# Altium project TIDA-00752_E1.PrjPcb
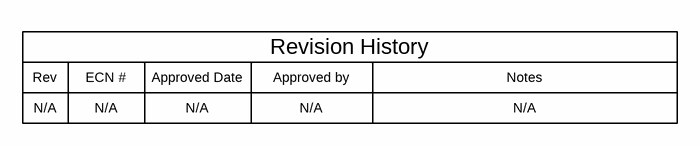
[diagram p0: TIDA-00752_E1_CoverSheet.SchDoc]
CopyrightYear: 2015; EVM_Orderable: N/A; PCB_Layout: SY; PCB_Rev: E1; PRJ_Customer: Public Release; PRJ_Engineer: SY; PRJ_Number: TIDA-00752; PRJ_Title: 2-Wire Galvanically Isolated IC Temperature Sensor with Pulse Count Interface; SCH_Rev: E1; TechSupport: http://www.ti.com/support; TID: TIDA-00752
3 sheets, 89 parts. Net scope: global (net labels, ports and power ports of the same name join across sheets).
Board file: TIDA-00752_E1_TID.PcbDoc
Sheets:
  TIDA-00752_E1_CoverSheet.SchDoc
  TIDA-00752_E1_MSP430_LMT01.SchDoc
  TIDA-00752_E1_TID_Hardware.SchDoc

## Sheet TIDA-00752_E1_CoverSheet.SchDoc: System Block Diagram
size 431 x 279 mm; Date: Not shown in title block; ApprovedBy: Not shown in title block; CheckedBy: Not shown in title block; Author: Not shown in title block; CompanyName: Not shown in title block; DrawnBy: SY; Engineer: Not shown in title block; Organization: Not shown in title block; Address1: Not shown in title block; Address2: Not shown in title block; Address3: Not shown in title block; Address4: Not shown in title block; DocumentNumber: 1; Revision: Use project parameter SCH_Rev; SheetNumber: 1; SheetTotal: 3; PageSetup: Record=PageOptions¦CenterHorizontal=True¦CenterVertical=True¦PrintScale=1.00¦XCorrection=1.00¦YCorrection=1.00¦PrintKind=0¦BorderSize=5000000¦LeftOffset=0¦BottomOffset=0¦Orientation=2¦PaperLength=1000¦PaperWidth=1000¦Scale=100¦PaperSource=15¦PrintQuality=600¦MediaType=1¦DitherType=10¦PaperKind=Letter¦PrintScaleMode=1

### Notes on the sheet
- Rev
- N/A
- ECN #
- Approved Date
- Approved by
- Revision History
- Notes

## Sheet TIDA-00752_E1_MSP430_LMT01.SchDoc: MSP430 MCU & LMT01 Interface Circuitry
size 431 x 279 mm; Date: Not shown in title block; ApprovedBy: Not shown in title block; CheckedBy: Not shown in title block; Author: Not shown in title block; CompanyName: Not shown in title block; DrawnBy: SY; Engineer: Not shown in title block; Organization: Not shown in title block; Address1: Not shown in title block; Address2: Not shown in title block; Address3: Not shown in title block; Address4: Not shown in title block; DocumentNumber: 1; Revision: Use project parameter SCH_Rev; SheetNumber: 2; SheetTotal: 3; PageSetup: Record=PageOptions¦CenterHorizontal=True¦CenterVertical=True¦PrintScale=1.00¦XCorrection=1.00¦YCorrection=1.00¦PrintKind=0¦BorderSize=5000000¦LeftOffset=0¦BottomOffset=0¦Orientation=2¦PaperLength=1000¦PaperWidth=1000¦Scale=100¦PaperSource=15¦PrintQuality=600¦MediaType=1¦DitherType=10¦PaperKind=Letter¦PrintScaleMode=1
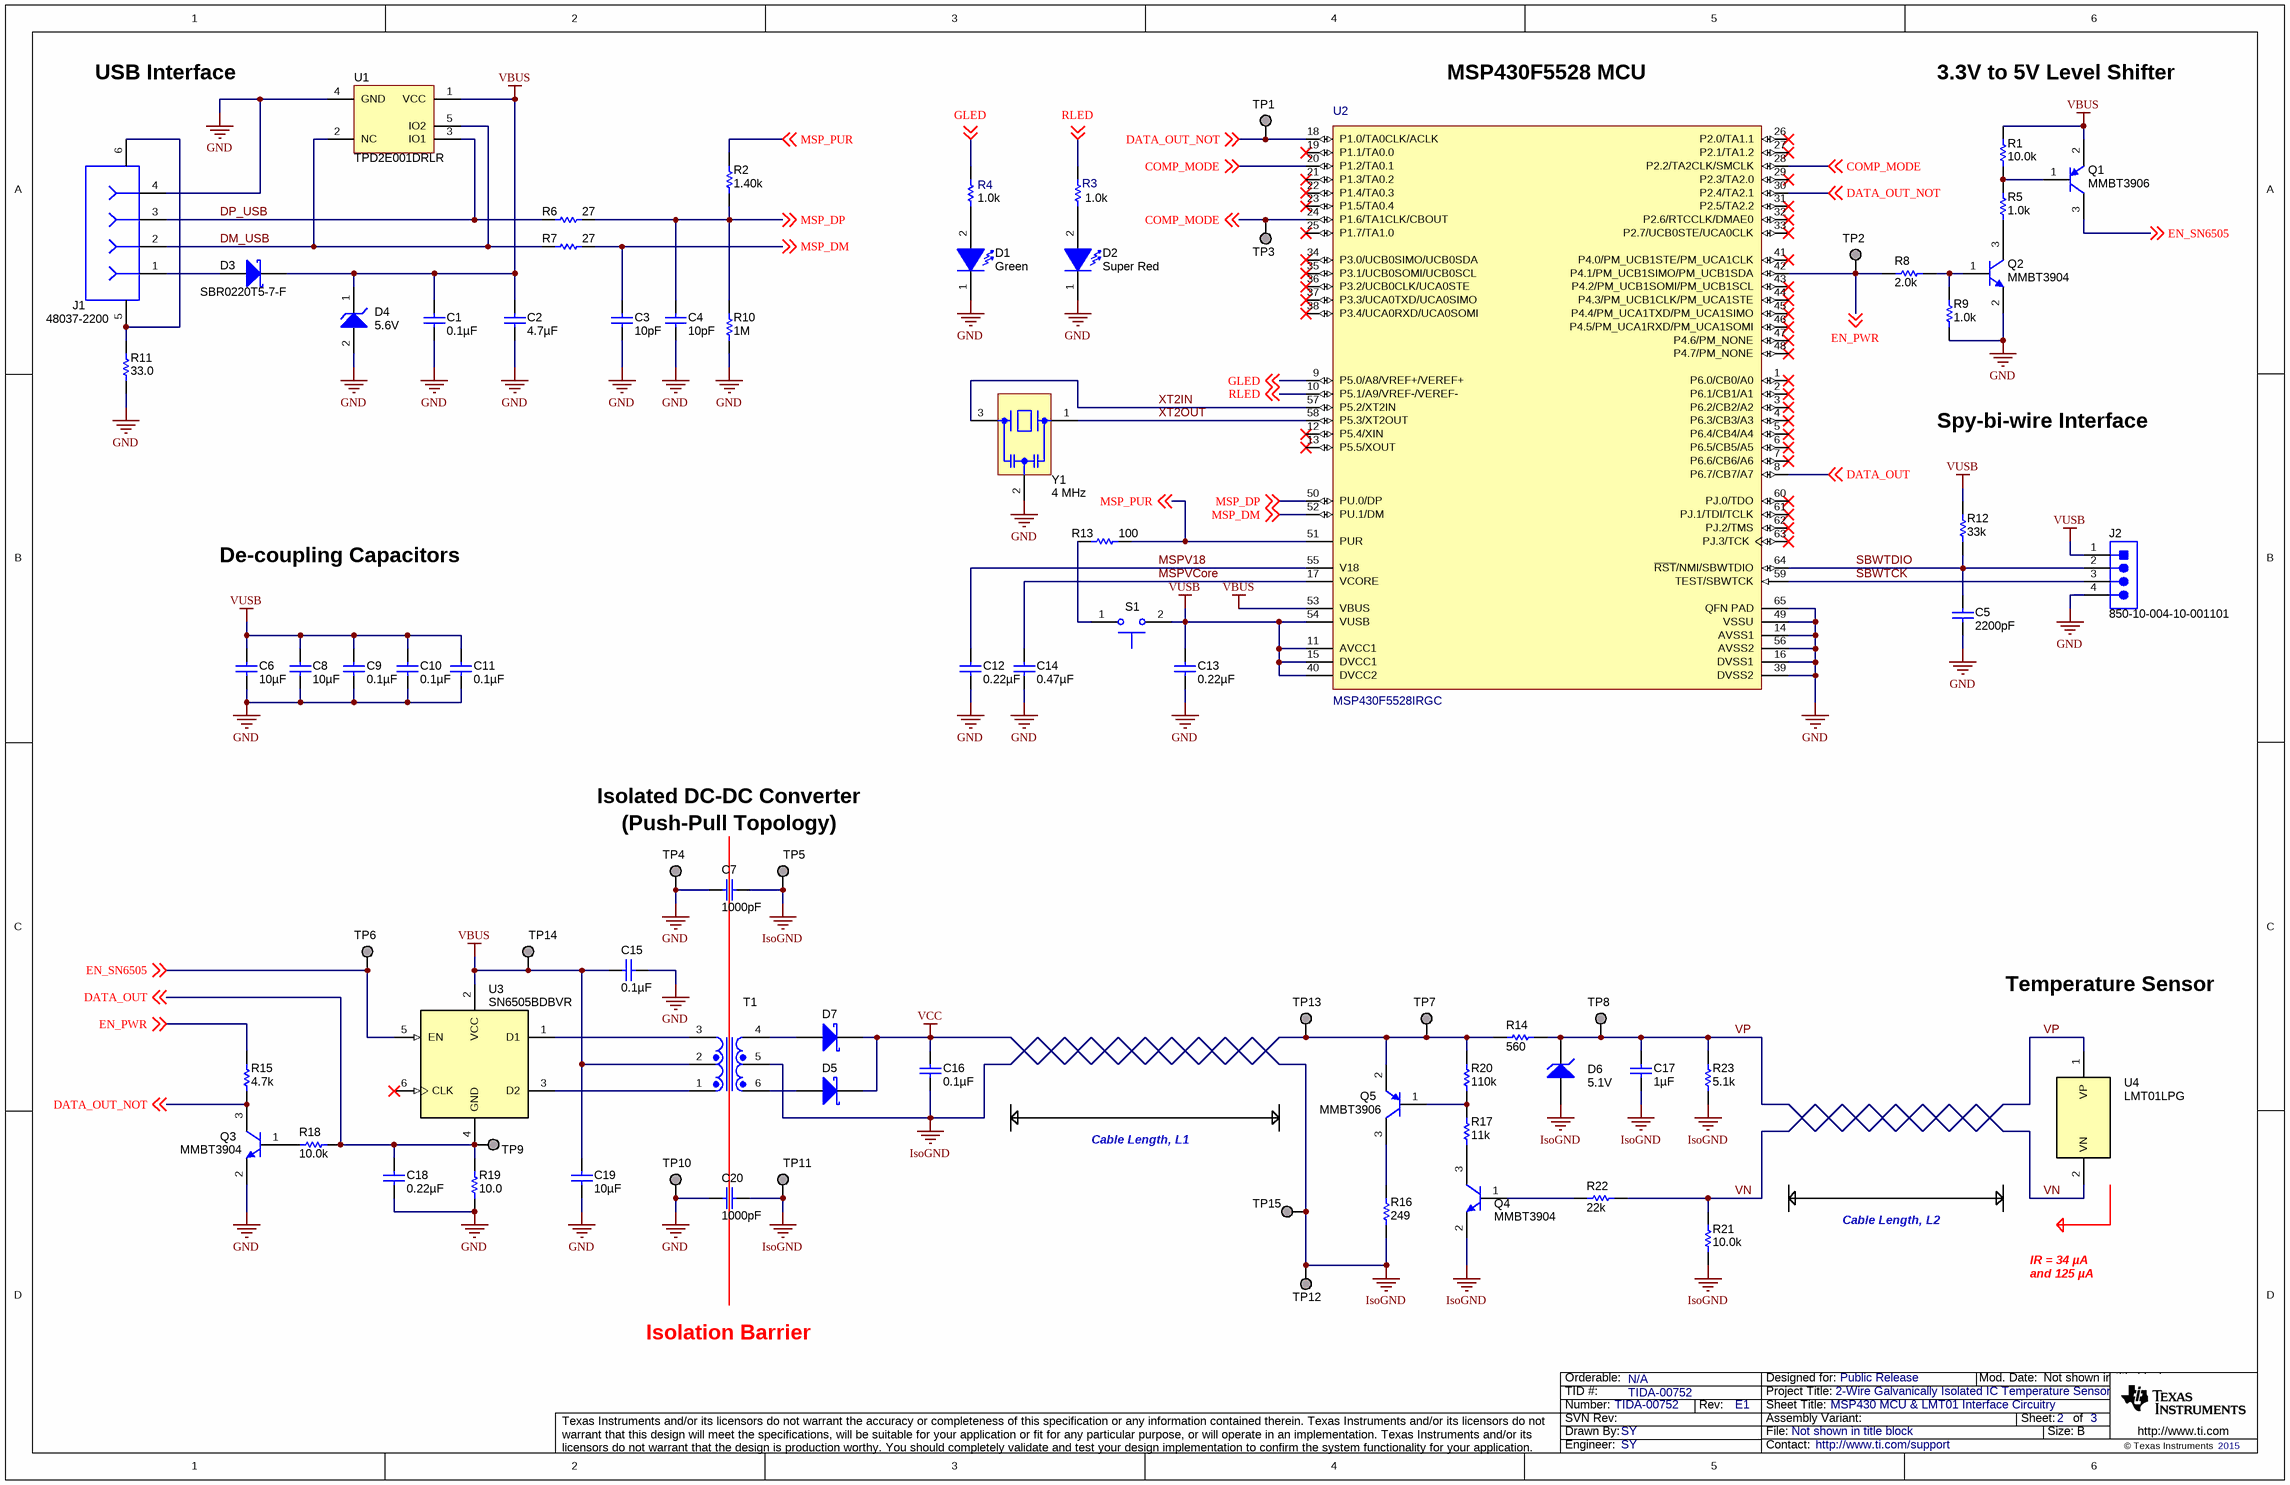
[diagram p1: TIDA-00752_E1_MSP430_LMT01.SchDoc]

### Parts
C1  ValueDisplayed: 0.1µF  [0402]  (hidden comment: C1005X7R1H104K050BB)
C2  ValueDisplayed: 4.7µF  [0603]  (hidden comment: 0603ZD475KAT2A)
C3  ValueDisplayed: 10pF  [0402]  (hidden comment: 500R07S100JV4T)
C4  ValueDisplayed: 10pF  [0402]  (hidden comment: 500R07S100JV4T)
C5  ValueDisplayed: 2200pF  [0402]  (hidden comment: GRM155R70J222KA01D)
C6  ValueDisplayed: 10µF  [0805_145]  (hidden comment: C2012X7R1A106K125AC)
C7  ValueDisplayed: 1000pF  [1206_190]  (hidden comment: 202R18W102KV4E)
C8  ValueDisplayed: 10µF  [0805_145]  (hidden comment: C2012X7R1A106K125AC)
C9  ValueDisplayed: 0.1µF  [0402]  (hidden comment: C1005X7R1H104K050BB)
C10  ValueDisplayed: 0.1µF  [0402]  (hidden comment: C1005X7R1H104K050BB)
C11  ValueDisplayed: 0.1µF  [0402]  (hidden comment: C1005X7R1H104K050BB)
C12  ValueDisplayed: 0.22µF  [0402]  (hidden comment: GRM155R61A224KE19D)
C13  ValueDisplayed: 0.22µF  [0402]  (hidden comment: GRM155R61A224KE19D)
C14  ValueDisplayed: 0.47µF  [0402]  (hidden comment: C1005X5R1A474K050BB)
C15  ValueDisplayed: 0.1µF  [0402]  (hidden comment: C1005X7R1H104K050BB)
C16  ValueDisplayed: 0.1µF  [0603]  (hidden comment: 06033C104JAT2A)
C17  ValueDisplayed: 1µF  [0603]  (hidden comment: GRM188R71A105KA61D)
C18  ValueDisplayed: 0.22µF  [0402]  (hidden comment: GRM155R71C224KA12D)
C19  ValueDisplayed: 10µF  [0805_145]  (hidden comment: EMK212BB7106MG-T)
C20  ValueDisplayed: 1000pF  [1206_190]  (hidden comment: 202R18W102KV4E)
D1  value Green  [WL-SMCW_GREEN]  (hidden comment: 150060VS75000)
D2  value Super Red  [WL-SMCW_RED]  (hidden comment: 150060SS75000)
D3  SBR0220T5-7-F  [SOD-523]
D4  value 5.6V  [SOD-123]  (hidden comment: MMSZ5232B-7-F)
D5  MBR0540T1G  [SOD-123]  (value not drawn)
D6  value 5.1V  [SOD-323F]  (hidden comment: D3Z5V1BF-7)
D7  MBR0540T1G  [SOD-123]  (value not drawn)
J1  48037-2200  [CONN_USB_0480372200]
J2  850-10-004-10-001101  [Preci-dip_850-xx-004-10-001101]
Q1  MMBT3906  [SOT-23]
Q2  MMBT3904  [SOT-23]
Q3  MMBT3904  [SOT-23]
Q4  MMBT3904  [SOT-23]
Q5  MMBT3906  [SOT-23]
R1  ValueDisplayed: 10.0k  [0402]  (hidden comment: CRCW040210K0FKED)
R2  ValueDisplayed: 1.40k  [0402]  (hidden comment: ERJ-2RKF1401X)
R3  value 1.0k  [0402]  (hidden comment: CRCW04021K00JNED)
R4  value 1.0k  [0402]  (hidden comment: CRCW04021K00JNED)
R5  ValueDisplayed: 1.0k  [0402]  (hidden comment: CRCW04021K00JNED)
R6  ValueDisplayed: 27  [0402]  (hidden comment: CRCW040227R0JNED)
R7  ValueDisplayed: 27  [0402]  (hidden comment: CRCW040227R0JNED)
R8  ValueDisplayed: 2.0k  [0402]  (hidden comment: CRCW04022K00JNED)
R9  ValueDisplayed: 1.0k  [0402]  (hidden comment: CRCW04021K00JNED)
R10  value 1M  [0402]  (hidden comment: CRCW04021M00JNED)
R11  ValueDisplayed: 33.0  [0603]  (hidden comment: CRCW060333R0FKEA)
R12  value 33k  [0402]  (hidden comment: CRCW040233K0JNED)
R13  ValueDisplayed: 100  [0402]  (hidden comment: ERJ-2RKF1000X)
R14  ValueDisplayed: 560  [0603]  (hidden comment: RC0603JR-07560RL)
R15  ValueDisplayed: 4.7k  [0402]  (hidden comment: CRCW04024K70JNED)
R16  ValueDisplayed: 249  [2512]  (hidden comment: CRCW2512249RFKEG)
R17  ValueDisplayed: 11k  [0402]  (hidden comment: CRCW040211K0JNED)
R18  ValueDisplayed: 10.0k  [0402]  (hidden comment: CRCW040210K0FKED)
R19  ValueDisplayed: 10.0  [0805_HV]  (hidden comment: RC0805FR-0710RL)
R20  ValueDisplayed: 110k  [0402]  (hidden comment: CRCW0402110KJNED)
R21  ValueDisplayed: 10.0k  [0402]  (hidden comment: CRCW040210K0FKED)
R22  ValueDisplayed: 22k  [0402]  (hidden comment: CRCW040222K0JNED)
R23  ValueDisplayed: 5.1k  [0402]  (hidden comment: CRCW04025K10JNED)
S1  SKRKAEE010  [SW_SKRKAEE010]  (value not drawn)
T1  760390014  [Wurth_760390013]  (value not drawn)
TP1  TESTPOINT  [TP_H045P075]  (value not drawn)  (no BOM)
TP2  TESTPOINT  [TP_H045P075]  (value not drawn)  (no BOM)
TP3  TESTPOINT  [TP_H045P075]  (value not drawn)  (no BOM)
TP4  TESTPOINT  [TP_H045P075]  (value not drawn)  (no BOM)
TP5  TESTPOINT  [TP_H045P075]  (value not drawn)  (no BOM)
TP6  TESTPOINT  [TP_H045P075]  (value not drawn)  (no BOM)
TP7  TESTPOINT  [TP_H045P075]  (value not drawn)  (no BOM)
TP8  TESTPOINT  [TP_H045P075]  (value not drawn)  (no BOM)
TP9  TESTPOINT  [TP_H045P075]  (value not drawn)  (no BOM)
TP10  TESTPOINT  [TP_H045P075]  (value not drawn)  (no BOM)
TP11  TESTPOINT  [TP_H045P075]  (value not drawn)  (no BOM)
TP12  TESTPOINT  [TP_H045P075]  (value not drawn)  (no BOM)
TP13  TESTPOINT  [TP_H045P075]  (value not drawn)  (no BOM)
TP14  TESTPOINT  [TP_H045P075]  (value not drawn)  (no BOM)
TP15  TESTPOINT  [TP_H045P075]  (value not drawn)  (no BOM)
U1  TPD2E001DRLR  [DRL0005A]
U2  MSP430F5528IRGC  [RGC0064B]
U3  SN6505BDBVR  [DBV0006A_N]
U4  LMT01LPG  [LPG0002A]
Y1  Frequency: 4 MHz  [Murata_CSTCR]  (hidden comment: CSTCR4M00G15L99-R0)

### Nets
GND: C1.2 C2.2 C3.2 C4.2 C5.2 C6.2 C7.2 C8.2 C9.2 C10.2 C11.2 C12.2 C13.2 C14.2 C15.2 C18.2 C19.2 C20.2 D1.1(K) D2.1(K) D4.2(A) J1.4 J2.4 Q2.2(E) Q3.2(E) R9.1 R10.1 R11.1 R19.1 TP4.1 TP10.1 U1.4(GND) U2.14(AVSS1) U2.16(DVSS1) U2.39(DVSS2) U2.49(VSSU) U2.56(AVSS2) U2.65(QFN_PAD) Y1.2(GND)
IsoGND: C7.1 C16.2 C17.2 C20.1 D6.2(A) Q4.2(E) R16.1 R21.2 R23.1 T1.5 TP5.1 TP11.1 TP12.1 TP15.1
VBUS: C1.1 C2.1 C15.1 C19.1 D3.1(K) D4.1(K) Q1.2(E) R1.1 T1.2 TP14.1 U1.1(VCC) U2.53(VBUS) U3.2(VCC)
VCC: C16.1 D5.1(K) D7.1(K) Q5.2(E) R14.1 R20.2 TP7.1 TP13.1
VUSB: C6.1 C8.1 C9.1 C10.1 C11.1 C13.1 J2.1 R12.1 S1.2 U2.11(AVCC1) U2.15(DVCC1) U2.40(DVCC2) U2.54(VUSB)
COMP_MODE: TP3.1 U2.20(P1.2/TA0.1) U2.24(P1.6/TA1CLK/CBOUT) U2.28(P2.2/TA2CLK/SMCLK) ; off-sheet COMP_MODE
DATA_OUT: C18.1 R18.2 R19.2 TP9.1 U2.8(P6.7/CB7/A7) U3.4(GND) ; off-sheet DATA_OUT
DATA_OUT_NOT: Q3.3(C) R15.1 TP1.1 U2.18(P1.0/TA0CLK/ACLK) U2.30(P2.4/TA2.1) ; off-sheet DATA_OUT_NOT
DM_USB: J1.2 R7.1 U1.2(NC) U1.5(IO2)
DP_USB: J1.3 R6.1 U1.3(IO1)
EN_PWR: R8.1 R15.2 TP2.1 U2.42(P4.1/PM_UCB1SIMO/PM_UCB1SDA) ; off-sheet EN_PWR
EN_SN6505: Q1.3(C) TP6.1 U3.5(EN) ; off-sheet EN_SN6505
GLED: R4.1 U2.9(P5.0/A8/VREF+/VEREF+) ; off-sheet GLED
MSP_DM: C3.1 R7.2 U2.52(PU.1/DM) ; off-sheet MSP_DM
MSP_DP: C4.1 R2.1 R6.2 R10.2 U2.50(PU.0/DP) ; off-sheet MSP_DP
MSP_PUR: R2.2 R13.1 U2.51(PUR) ; off-sheet MSP_PUR
MSPV18: C12.1 U2.55(V18)
MSPVCore: C14.1 U2.17(VCORE)
RLED: R3.1 U2.10(P5.1/A9/VREF-/VEREF-) ; off-sheet RLED
SBWTCK: J2.3 U2.59(TEST/SBWTCK)
SBWTDIO: C5.1 J2.2 R12.2 U2.64(~{RST}/NMI/SBWTDIO)
VN: R21.1 R22.2 U4.2(VN)
VP: C17.1 D6.1(K) R14.2 R23.2 TP8.1 U4.1(VP)
XT2IN: U2.57(P5.2/XT2IN) Y1.3(Out)
XT2OUT: U2.58(P5.3/XT2OUT) Y1.1(In)
NetD1_2: D1.2(A) R4.2
NetD2_2: D2.2(A) R3.2
NetD3_2: D3.2(A) J1.1
NetD5_2: D5.2(A) T1.6
NetD7_2: D7.2(A) T1.4
NetJ1_5: J1.5 J1.6 R11.2
NetQ1_1: Q1.1(B) R1.2 R5.2
NetQ2_1: Q2.1(B) R8.2 R9.2
NetQ2_3: Q2.3(C) R5.1
NetQ3_1: Q3.1(B) R18.1
NetQ4_1: Q4.1(B) R22.1
NetQ4_3: Q4.3(C) R17.1
NetQ5_1: Q5.1(B) R17.2 R20.1
NetQ5_3: Q5.3(C) R16.2
NetR13_2: R13.2 S1.1
NetT1_1: T1.1 U3.3(D2)
NetT1_3: T1.3 U3.1(D1)

Not connected (* = marked no-connect by the designer): U2 1(P6.0/CB0/A0)* 2(P6.1/CB1/A1)* 3(P6.2/CB2/A2)* 4(P6.3/CB3/A3)* 5(P6.4/CB4/A4)* 6(P6.5/CB5/A5)* 7(P6.6/CB6/A6)* 12(P5.4/XIN)* 13(P5.5/XOUT)* 19(P1.1/TA0.0)* 21(P1.3/TA0.2)* 22(P1.4/TA0.3)* 23(P1.5/TA0.4)* 25(P1.7/TA1.0)* 26(P2.0/TA1.1)* 27(P2.1/TA1.2)* 29(P2.3/TA2.0)* 31(P2.5/TA2.2)* 32(P2.6/RTCCLK/DMAE0)* 33(P2.7/UCB0STE/UCA0CLK)* 34(P3.0/UCB0SIMO/UCB0SDA)* 35(P3.1/UCB0SOMI/UCB0SCL)* 36(P3.2/UCB0CLK/UCA0STE)* 37(P3.3/UCA0TXD/UCA0SIMO)* 38(P3.4/UCA0RXD/UCA0SOMI)* 41(P4.0/PM_UCB1STE/PM_UCA1CLK)* 43(P4.2/PM_UCB1SOMI/PM_UCB1SCL)* 44(P4.3/PM_UCB1CLK/PM_UCA1STE)* 45(P4.4/PM_UCA1TXD/PM_UCA1SIMO)* 46(P4.5/PM_UCA1RXD/PM_UCA1SOMI)* 47(P4.6/PM_NONE)* 48(P4.7/PM_NONE)* 60(PJ.0/TDO)* 61(PJ.1/TDI/TCLK)* 62(PJ.2/TMS)* 63(PJ.3/TCK)*; U3 6(CLK)*

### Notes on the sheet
- USB Interface
- MSP430F5528 MCU
- 3.3V to 5V Level Shifter
- Spy-bi-wire Interface
- De-coupling Capacitors
- Isolated DC-DC Converter
- (Push-Pull Topology)
- Temperature Sensor
- Cable Length, L1
- Cable Length, L2
- IR = 34 µA
  and 125 µA
- Isolation Barrier

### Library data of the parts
C1 C9-C11 C15 = C1005X7R1H104K050BB: CAP, CERM, 0.1 µF, 50 V, +/- 10%, X7R, 0402; Manufacturer: TDK; Polarized: N; CompType: Capacitor; Value: 0.1uF; U/M: EA; Cap_F: 0.0000001; Tolerance_%: 10; Value1: Unknown; VDC_V: 50; Value2: 50V; TaMin_C: -55; TaMax_C: 125
C2 = 0603ZD475KAT2A: CAP, CERM, 4.7 µF, 10 V, +/- 10%, X5R, 0603; Manufacturer: AVX; Polarized: N; CompType: Capacitor; Value: 4.7uF; U/M: EA; Cap_F: 0.0000047; Tolerance_%: 10; Value1: Unknown; Value2: 10V; TaMin_C: -55; TaMax_C: 85; AEC Category: Q200
C3 C4 = 500R07S100JV4T: CAP, CERM, 10 pF, 50 V, +/- 5%, C0G/NP0, 0402; Manufacturer: Johanson Technology; Polarized: N; CompType: Capacitor; Value: 10pF; U/M: EA; Cap_F: 0.00000000001; Tolerance_%: 5; Value1: Unknown; VDC_V: 50; Value2: 50V; TaMin_C: -55; TaMax_C: 125
C5 = GRM155R70J222KA01D: CAP, CERM, 2200pF, 6.3V, +/-10%, X7R, 0402; Manufacturer: MuRata; Polarized: N; CompType: Capacitor; U/M: EA; Cap_F: 0.0000000022; Tolerance_%: 10; Value1: Unknown; VDC_V: 6.3; TaMin_C: -55; TaMax_C: 125
C6 C8 = C2012X7R1A106K125AC: CAP, CERM, 10 µF, 10 V, +/- 10%, X7R, 0805; Manufacturer: TDK; Polarized: N; CompType: Capacitor; Value: 10uF; U/M: EA; Cap_F: 0.00001; Tolerance_%: 10; Value1: Unknown; Value2: 10V; TaMin_C: -55; TaMax_C: 125; Cap_Case: 0805; AEC Category: Q200
C7 C20 = 202R18W102KV4E: CAP, CERM, 1000 pF, 2000 V, +/- 10%, X7R, 1206_190; Manufacturer: Johanson Technology; Polarized: N; CompType: Capacitor; Value: 1000pF; U/M: EA; Cap_F: 0.000000001; Tolerance_%: 10; Value1: Unknown; VDC_V: 2000; Value2: 2000V; TaMin_C: -55; TaMax_C: 125; Cap_Case: 1206; AEC Category: Q200
C12 C13 = GRM155R61A224KE19D: CAP, CERM, 0.22 µF, 10 V, +/- 10%, X5R, 0402; Manufacturer: MuRata; Polarized: N; CompType: Capacitor; Value: 0.22uF; U/M: EA; Cap_F: 0.00000022; Tolerance_%: 10; Value1: Unknown; Value2: 10V; TaMin_C: -55; TaMax_C: 85; AEC Category: Q200
C14 = C1005X5R1A474K050BB: CAP, CERM, 0.47 µF, 10 V, +/- 10%, X5R, 0402; Manufacturer: TDK; Polarized: N; CompType: Capacitor; Value: 0.47uF; U/M: EA; Cap_F: 0.00000047; Tolerance_%: 10; Value1: Unknown; Value2: 10V; TaMin_C: -55; TaMax_C: 85; AEC Category: Q200
C16 = 06033C104JAT2A: CAP, CERM, 0.1 µF, 25 V, +/- 5%, X7R, 0603; Manufacturer: AVX; Polarized: N; CompType: Capacitor; Value: 0.1uF; U/M: EA; Cap_F: 0.0000001; Tolerance_%: 5; ESR_ohm: 0.05; Value1: 0.05 ohm; VDC_V: 25; Value2: 25V; TaMin_C: -55; TaMax_C: 125; AEC Category: Q200
C17 = GRM188R71A105KA61D: CAP, CERM, 1 µF, 10 V, +/- 10%, X7R, 0603; Manufacturer: MuRata; Polarized: N; CompType: Capacitor; Value: 1uF; U/M: EA; Cap_F: 0.000001; Tolerance_%: 10; ESR_ohm: 0.011; Value1: 0.011 ohm; Value2: 10V; TaMin_C: -55; TaMax_C: 125; AEC Category: Q200
C18 = GRM155R71C224KA12D: CAP, CERM, 0.22 µF, 16 V, +/- 10%, X7R, 0402; Manufacturer: MuRata; Polarized: N; CompType: Capacitor; Value: 0.22uF; U/M: EA; Cap_F: 0.00000022; Tolerance_%: 10; Value1: Unknown; VDC_V: 16; Value2: 16V; TaMin_C: -55; TaMax_C: 125; AEC Category: Q200
C19 = EMK212BB7106MG-T: CAP, CERM, 10 µF, 16 V, +/- 20%, X7R, 0805; Manufacturer: Taiyo Yuden; Polarized: N; CompType: Capacitor; Value: 10uF; U/M: EA; Cap_F: 0.00001; Tolerance_%: 20; Value1: Unknown; VDC_V: 16; Value2: 16V; TaMin_C: -55; TaMax_C: 125; Cap_Case: 0805; AEC Category: Q200
D1 = 150060VS75000: LED, Green, SMD; Manufacturer: Wurth Elektronik eiSos; Type: AlInGaP; Vf_V: 2; Value2: 2V; Io_A: 0.02; Value1: W; U/M: EA
D2 = 150060SS75000: LED, Super Red, SMD; Manufacturer: Wurth Elektronik eiSos; Type: AlInGaP; Vf_V: 1.9; Value2: 1.9V; Io_A: 0.02; Value1: W; U/M: EA
D3 = SBR0220T5-7-F: Diode, Schottky, 20 V, 0.2 A, SOD-523; Manufacturer: Diodes Inc.; U/M: EA; Vf_V: 0.47; Value: 20V; Value1: 0.2A; Value2: 0.47V; Io_A: 0.2; Vr_V: 20
D4 = MMSZ5232B-7-F: Diode, Zener, 5.6V, 500mW, SOD-123; Manufacturer: Diodes Inc.; U/M: EA; Power_W: 0.5; Vz_V: 5.6; Value1: 0.5W; RJA_CperW: 350
D5 D7 = MBR0540T1G: Diode, Schottky, 40 V, 0.5 A, SOD-123; Manufacturer: ON Semiconductor; U/M: EA; Vf_V: 0.51; Value: 40V; Value1: 0.5A; Value2: 0.51V; Io_A: 0.5; Vr_V: 40; TJmax_C: 150; RJC_CperW: 118; AEC Category: Q101
D6 = D3Z5V1BF-7: Diode, Zener, 5.1 V, 400 mW, SOD-323F; Manufacturer: Diodes Inc.; SymbolCreator: a0412235; U/M: EA; Power_W: 0.4; Vz_V: 5.1; Value1: 0.4W; RJA_CperW: 313; AEC Category: Q101
J1 = 48037-2200: Connector, Plug, USB Type A, R/A, Top Mount SMT; Manufacturer: Molex; SymbolCreator: a0412235; U/M: EA
J2 = 850-10-004-10-001101: Header, 50mil, 4x1, Gold, TH; Manufacturer: Preci-Dip; SymbolCreator: a0412235; U/M: EA
Q1 Q5 = MMBT3906, Fairchild Semiconductor: Transistor, PNP, 40 V, 0.2 A, SOT-23; CompType: BJT; PNP: 1; NPN: 0; Vceo_V: 40; Vcesat1_V: 0.25; Value: 40 V; IcRated_A: 0.2; Value1: 0.2 A; HfeMax: 300; TaMin_C: -55; TaMax_C: 150; U/M: EA; AEC Category: Q101
Q2-Q4 = MMBT3904, Fairchild Semiconductor: Transistor, NPN, 40 V, 0.2 A, SOT-23; CompType: BJT; PNP: 0; NPN: 1; Vceo_V: 40; Vcesat1_V: 0.2; Value: 40 V; Value1: 0.2 A; HfeMax: 300; TaMin_C: -55; TaMax_C: 150; U/M: EA; AEC Category: Q101
R1 R18 R21 = CRCW040210K0FKED: RES, 10.0 k, 1%, 0.063 W, 0402; Manufacturer: Vishay-Dale; CompType: Resistor; Value: 10.0k; Res_ohm: 10000; Value_Code: 10k0; Tolerance_%: 1; Power_W: 0.063; Value2: 0.063W; VDC_V: 50; TempCo: 100 ppm/C; EIA_Code: E96; U/M: EA; AEC Category: Q200
R2 = ERJ-2RKF1401X: RES, 1.40 k, 1%, 0.1 W, 0402; Manufacturer: Panasonic; CompType: Resistor; Value: 1.40k; Res_ohm: 1400; Value_Code: 1k40; Tolerance_%: 1; Power_W: 0.1; Value2: 0.1W; VDC_V: 50; TempCo: 100 ppm/C; EIA_Code: E96; U/M: EA
R3 R4 = CRCW04021K00JNED: RES, 1.0k ohm, 5%, 0.063W, 0402; Manufacturer: Vishay-Dale; CompType: Resistor; Res_ohm: 1000; Value_Code: 1k00; Tolerance_%: 5; Power_W: 0.063; VDC_V: 50; TempCo: 200 ppm/C; EIA_Code: E24; U/M: EA
R5 R9 = CRCW04021K00JNED: RES, 1.0 k, 5%, 0.063 W, 0402; Manufacturer: Vishay-Dale; CompType: Resistor; Value: 1.0k; Res_ohm: 1000; Value_Code: 1k00; Tolerance_%: 5; Power_W: 0.063; Value2: 0.063W; VDC_V: 50; TempCo: 200 ppm/C; EIA_Code: E24; U/M: EA; AEC Category: Q200
R6 R7 = CRCW040227R0JNED: RES, 27, 5%, 0.063 W, 0402; Manufacturer: Vishay-Dale; CompType: Resistor; Value: 27; Value_Code: 27R0; Tolerance_%: 5; Power_W: 0.063; Value2: 0.063W; VDC_V: 50; TempCo: 200 ppm/C; EIA_Code: E24; U/M: EA
R8 = CRCW04022K00JNED: RES, 2.0 k, 5%, 0.063 W, 0402; Manufacturer: Vishay-Dale; CompType: Resistor; Value: 2.0k; Res_ohm: 2000; Value_Code: 2k00; Tolerance_%: 5; Power_W: 0.063; Value2: 0.063W; VDC_V: 50; TempCo: 200 ppm/C; EIA_Code: E24; U/M: EA; AEC Category: Q200
R10 = CRCW040233K0JNED: RES,1M ohm, 5%, 0.063W, 0402; Manufacturer: Yageo; CompType: Resistor; Res_ohm: 1000000; Tolerance_%: 5; Power_W: 0.063; VDC_V: 50; TempCo: 200 ppm/C; EIA_Code: E24; U/M: EA
R11 = CRCW060333R0FKEA: RES, 33.0, 1%, 0.1 W, 0603; Manufacturer: Vishay-Dale; CompType: Resistor; Value: 33.0; Res_ohm: 33; Value_Code: 33R0; Tolerance_%: 1; Power_W: 0.1; Value2: 0.1W; VDC_V: 75; TempCo: 100 ppm/C; U/M: EA; AEC Category: Q200
R12 = CRCW040233K0JNED: RES, 33k ohm, 5%, 0.063W, 0402; Manufacturer: Vishay-Dale; CompType: Resistor; Res_ohm: 33000; Value_Code: 33k0; Tolerance_%: 5; Power_W: 0.063; VDC_V: 50; TempCo: 200 ppm/C; EIA_Code: E24; U/M: EA
R13 = ERJ-2RKF1000X: RES, 100, 1%, 0.1 W, 0402; Manufacturer: Panasonic; CompType: Resistor; Value: 100; Value_Code: 100R; Tolerance_%: 1; Power_W: 0.1; Value2: 0.1W; VDC_V: 50; TempCo: 100 ppm/C; EIA_Code: E96; U/M: EA
R14 = RC0603JR-07560RL: RES, 560, 5%, 0.1 W, 0603; Manufacturer: Yageo America; CompType: Resistor; Value: 560; Value_Code: 560R; Tolerance_%: 5; Power_W: 0.1; Value2: 0.1W; VDC_V: 50; TempCo: 100 ppm/C; EIA_Code: E24; U/M: EA; AEC Category: Q200
R15 = CRCW04024K70JNED: RES, 4.7 k, 5%, 0.063 W, 0402; Manufacturer: Vishay-Dale; CompType: Resistor; Value: 4.7k; Res_ohm: 4700; Value_Code: 4k70; Tolerance_%: 5; Power_W: 0.063; Value2: 0.063W; VDC_V: 50; TempCo: 200 ppm/C; EIA_Code: E24; U/M: EA; AEC Category: Q200
R16 = CRCW2512249RFKEG: RES, 249, 1%, 1 W, 2512; Manufacturer: Vishay-Dale; CompType: Resistor; Value: 249; Value_Code: 249R; Tolerance_%: 1; Value2: 1W; VDC_V: 500; TempCo: 100 ppm/C; EIA_Code: E96; U/M: EA; AEC Category: Q200
R17 = CRCW040211K0JNED: RES, 11 k, 5%, 0.063 W, 0402; Manufacturer: Vishay-Dale; CompType: Resistor; Value: 11k; Res_ohm: 11000; Value_Code: 11k0; Tolerance_%: 5; Power_W: 0.063; Value2: 0.063W; VDC_V: 50; TempCo: 200 ppm/C; EIA_Code: E24; U/M: EA; AEC Category: Q200
R19 = RC0805FR-0710RL: RES, 10.0, 1%, 0.125 W, 0805; Manufacturer: Yageo America; CompType: Resistor; Value: 10.0; Res_ohm: 10; Value_Code: 10R0; Tolerance_%: 1; Power_W: 0.125; Value2: 0.125W; VDC_V: 150; TempCo: 200 ppm/C; EIA_Code: E96; U/M: EA; AEC Category: Q200
R20 = CRCW0402110KJNED: RES, 110 k, 5%, 0.063 W, 0402; Manufacturer: Vishay-Dale; CompType: Resistor; Value: 110k; Res_ohm: 110000; Tolerance_%: 5; Power_W: 0.063; Value2: 0.063W; VDC_V: 50; TempCo: 200 ppm/C; EIA_Code: E24; U/M: EA; AEC Category: Q200
R22 = CRCW040222K0JNED: RES, 22 k, 5%, 0.063 W, 0402; Manufacturer: Vishay-Dale; CompType: Resistor; Value: 22k; Res_ohm: 22000; Value_Code: 22k0; Tolerance_%: 5; Power_W: 0.063; Value2: 0.063W; VDC_V: 50; TempCo: 200 ppm/C; EIA_Code: E24; U/M: EA; AEC Category: Q200
R23 = CRCW04025K10JNED: RES, 5.1 k, 5%, 0.063 W, 0402; Manufacturer: Vishay-Dale; CompType: Resistor; Value: 5.1k; Res_ohm: 5100; Value_Code: 5k10; Tolerance_%: 5; Power_W: 0.063; Value2: 0.063W; VDC_V: 50; TempCo: 200 ppm/C; EIA_Code: E24; U/M: EA; AEC Category: Q200
S1 = SKRKAEE010: Switch, Push Button, SMD; Manufacturer: Alps; SymbolCreator: a0412235; Circuit: SPST-NO; VDC_V: 12; SwitchFunction: Off-Mom; PositionCount: 1; CurrentRating_mA: 50
T1 = 760390014: Transformer, 475uH, SMT; Manufacturer: Wurth Elektronik; SymbolCreator: a0799628; DCR_Ohm: 0.31; U/M: EA
TP1-TP15 = TP_H0.45P0.75: Manufacturer: Texas Instruments; CompType: Pad
U1 = TPD2E001DRLR: Low-Capacitance + / - 15 kV ESD-Protection Array for High-Speed Data Interfaces, 2 Channels, -40 to +85 degC, 5-pin SOT (DRL), Green (RoHS & no Sb/Br); Manufacturer: Texas Instruments; Alternate Manufacturer: None; Alternate PartNumber: Equivalent; Breakdown Voltage(Min)(V): 11; IEC 61000-4-2 Air-Gap(+/- kV): 15; IEC 61000-4-2 Contact(+/- kV): 8; IO Capacitance(Typ)(pF): 1.5; IO Leakage Current(nA): 1; SubFamily: ESD Solution; USB High Speed: TRUE
U2 = MSP430F5528IRGC: Mixed Signal MicroController, RGC0064B; Manufacturer: Texas Instruments; Alternate Manufacturer: None; ADC: 12-bit SAR; ADC Channels: 16; Brown Out Reset: Yes; DMA: 3; Eco-Plan: Green (RoHS & no Sb/Br); Flash(KB): 128; Frequency(MHz): 25; GPIO: 47; Multiplier: 32x32; SRAM(B): 8192; SubFamily: 5 Series; Timers - 16-bit: 4; USB: 1; USCI_A (UART/LIN/IrDA/SPI): 2; SymbolCreator: Altium/a0412235; CompType: IC; U/M: EA
U3 = SN6505BDBVR: LOW-NOISE 1A TRANSFORMER DRIVERS FOR ISOLATED POWER SUPPLIES, DBV0006A; Alternate PartNumber: SN6505BDBVT; Manufacturer: Texas Instruments; SymbolCreator: Altium; CompType: IC; U/M: EA
U4 = LMT01LPG: 0.5°C Accurate 2-Pin Digital NTC or PTC Thermistor Replacement, LPG0002A; Manufacturer: Texas Instruments; SymbolCreator: a0799628; CompType: IC; U/M: EA
Y1 = CSTCR4M00G15L99-R0: Resonator, 4MHz, 39pF SMD; Manufacturer: MuRata; SymbolCreator: a0799721; U/M: EA; TaMin_C: 0; TaMax_C: 70; Frequency Stability: ±0.08 %

## Sheet TIDA-00752_E1_TID_Hardware.SchDoc: Hardware Items
size 431 x 279 mm; Date: Not shown in title block; ApprovedBy: Not shown in title block; CheckedBy: Not shown in title block; Author: Not shown in title block; CompanyName: Not shown in title block; DrawnBy: SY; Engineer: Not shown in title block; Organization: Not shown in title block; Address1: Not shown in title block; Address2: Not shown in title block; Address3: Not shown in title block; Address4: Not shown in title block; DocumentNumber: 1; Revision: Use project parameter SCH_Rev; SheetNumber: 3; SheetTotal: 3; PageSetup: Record=PageOptions¦CenterHorizontal=True¦CenterVertical=True¦PrintScale=1.00¦XCorrection=1.00¦YCorrection=1.00¦PrintKind=0¦BorderSize=5000000¦LeftOffset=0¦BottomOffset=0¦Orientation=2¦PaperLength=1000¦PaperWidth=1000¦Scale=100¦PaperSource=15¦PrintQuality=600¦MediaType=1¦DitherType=10¦PaperKind=Letter¦PrintScaleMode=1
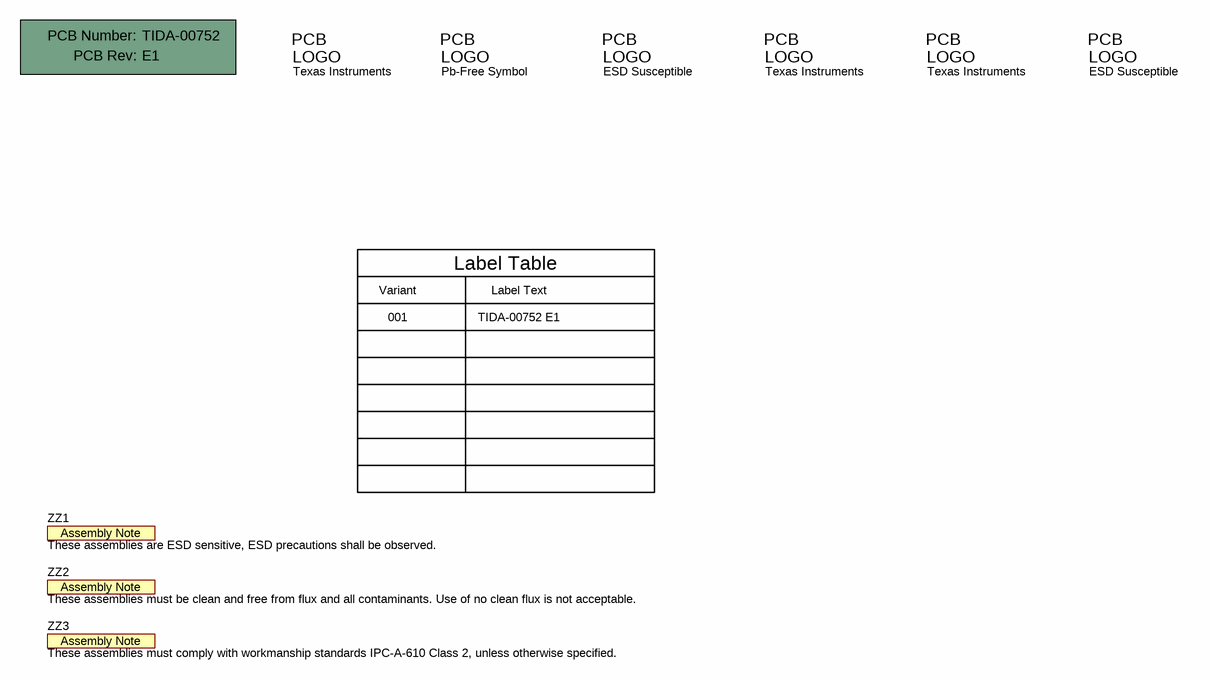
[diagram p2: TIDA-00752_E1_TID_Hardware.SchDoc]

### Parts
!PCB1  Printed Circuit Board  (value not drawn)  (mechanical)
Logo1  Texas Instruments  [TI_Stacked_Overlay_Small]  (no BOM)
Logo2  Pb-Free Symbol  [Pb-Free_Overlay_Small]  (no BOM)
Logo3  Texas Instruments  [TI_Symbol_Overlay_Small]  (no BOM)
Logo4  ESD Susceptible  [ESD_Overlay_Small]  (no BOM)
Logo5  Texas Instruments  [TI_Symbol_Overlay_Small]  (no BOM)
Logo6  ESD Susceptible  [ESD_Overlay_Small]  (no BOM)
ZZ1  These assemblies are ESD sensitive, ESD precautions shall be observed.  [AssemblyNote]  (no BOM)
ZZ2  These assemblies must be clean and free from flux and all contaminants. Use of no clean flux is not acceptable.  [AssemblyNote]  (no BOM)
ZZ3  These assemblies must comply with workmanship standards IPC-A-610 Class 2, unless otherwise specified.  [AssemblyNote]  (no BOM)

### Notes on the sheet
- Variant
- Label Table
- Label Text
- 001
- TIDA-00752 E1

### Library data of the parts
!PCB1 = PCB: Manufacturer: Any; PartNumber: TIDA-00752; SymbolCreator: a0412235
Logo1 = TI_Logo: Texas Instrument Corporate Signature; SymbolCreator: codlsc
Logo2 = Pb-Free: SymbolCreator: a0412235
Logo3 Logo5 = TI_Logo: Texas Instrument Corporate Signature; SymbolCreator: a0412235
Logo4 Logo6 = ESD_Susceptible: ESD Susceptible Symbol; SymbolCreator: a0412235
ZZ1-ZZ3 = AssemblyNote: SymbolCreator: codlsc

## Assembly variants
001: not fitted C7 C20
